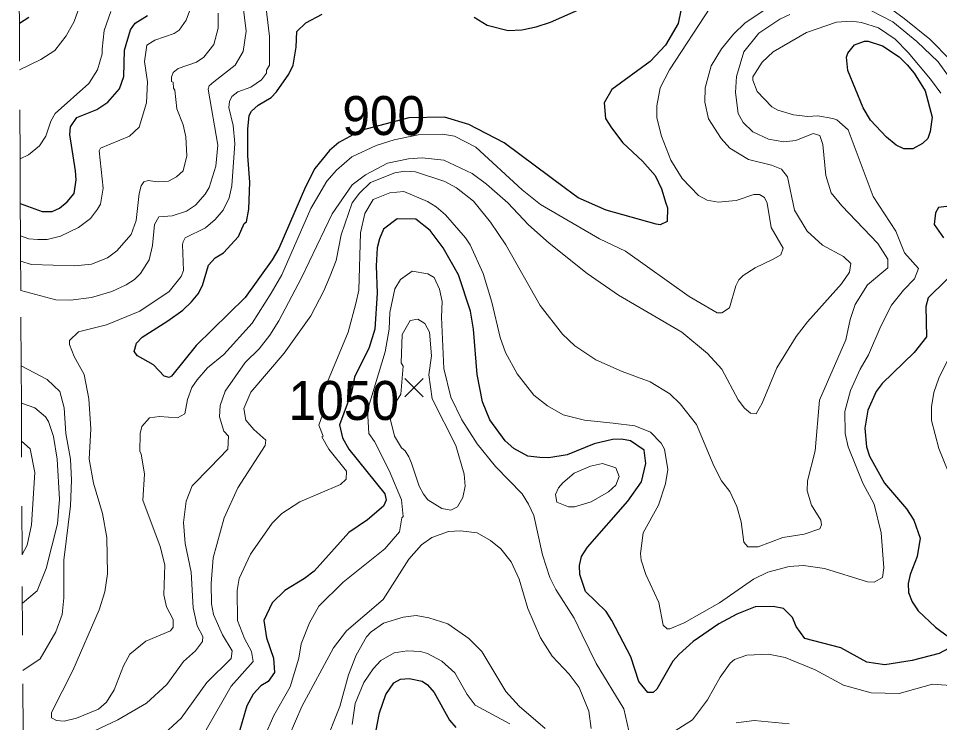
# Model space of a CAD drawing. Extents: x 423 to 448.8, y 7456.3 to 7484.
# Drawn here: x 423.014 to 424.902, y 7477.935 to 7479.378 of the extents above; entities that cross this region are included whole.
import ezdxf
from ezdxf.enums import TextEntityAlignment as Align

# ---------------------------------------------------------------- set-up
doc = ezdxf.new("R2010")
doc.units = 0
doc.header["$LTSCALE"] = 0.032
doc.linetypes.add('SHORT_DASHED', pattern=[2.7, 1.5, -1.2])
for name, color, linetype, lineweight in [('1', 7, 'Continuous', 25), ('2', 7, 'Continuous', 13), ('21', 7, 'Continuous', 25), ('22', 7, 'SHORT_DASHED', 13)]:
    doc.layers.add(name, color=color, linetype=linetype, lineweight=lineweight)
doc.layers.add('61', color=7, linetype='Continuous')

msp = doc.modelspace()

# ---------------------------------------------------------------- linework, layer by layer
at = {"layer": '1'}
for points in [[(423.9483, 7479.3807), (423.9746, 7479.3645), (424.0179, 7479.3536), (424.0458, 7479.3551), (424.0752, 7479.3614), (424.1046, 7479.3706), (424.1974, 7479.4116)], [(423.0356, 7479.3799), (423.0163, 7479.3681)], [(423.0182, 7478.9991), (423.0627, 7478.9824), (423.0697, 7478.9824), (423.0835, 7478.9827), (423.0983, 7478.9893), (423.1141, 7479.0025), (423.1284, 7479.0195), (423.1323, 7479.0473), (423.1315, 7479.0659), (423.1199, 7479.1402), (423.1207, 7479.1564), (423.1338, 7479.1749), (423.1749, 7479.1919), (423.1973, 7479.2067), (423.2213, 7479.2337), (423.2305, 7479.2593), (423.232, 7479.3134), (423.2437, 7479.3552), (423.2537, 7479.3683), (423.2785, 7479.3845)], [(424.3714, 7479.3946), (424.366, 7479.3676), (424.3404, 7479.3234), (424.3087, 7479.2902), (424.2306, 7479.2329), (424.2144, 7479.2051), (424.2175, 7479.1734), (424.2298, 7479.1541), (424.253, 7479.1231), (424.2932, 7479.086), (424.3188, 7479.0566), (424.3319, 7479.0288), (424.3413, 7478.9997), (424.3443, 7478.9901), (424.3435, 7478.9622), (424.3296, 7478.9553), (424.3211, 7478.9568), (424.219, 7478.9855), (424.161, 7479.0102), (424.1354, 7479.0295), (424.0094, 7479.1231), (423.9375, 7479.161), (423.8875, 7479.176), (423.8143, 7479.1747), (423.7163, 7479.1485), (423.6706, 7479.1239), (423.652, 7479.1076), (423.6219, 7479.0706), (423.6025, 7479.0334), (423.5476, 7478.9066), (423.5345, 7478.8833), (423.4788, 7478.806), (423.3783, 7478.7078), (423.328, 7478.6451), (423.3233, 7478.642), (423.3133, 7478.6451), (423.2908, 7478.6683), (423.2584, 7478.6869), (423.2514, 7478.6954), (423.2561, 7478.7124), (423.2676, 7478.7248), (423.3202, 7478.7581), (423.3512, 7478.7805), (423.369, 7478.7975), (423.3829, 7478.8138), (423.3914, 7478.8308), (423.4038, 7478.8725), (423.4177, 7478.8872), (423.4347, 7478.898), (423.4656, 7478.9313), (423.4772, 7478.9576), (423.4819, 7478.9615), (423.4865, 7478.987), (423.4888, 7479.0427), (423.4842, 7479.0968), (423.4842, 7479.151), (423.4873, 7479.1796), (423.492, 7479.1881), (423.5059, 7479.2005), (423.5322, 7479.2159), (423.543, 7479.2275), (423.5685, 7479.2639), (423.577, 7479.2825), (423.5832, 7479.3196), (423.5847, 7479.3513), (423.6034, 7479.3691), (423.6366, 7479.3869)], [(424.9275, 7478.994), (424.8997, 7478.9909), (424.8935, 7478.98), (424.8911, 7478.9561), (424.9097, 7478.9282)], [(424.0295, 7478.4966), (424.0117, 7478.5121), (423.98, 7478.5554), (423.9653, 7478.5926), (423.9545, 7478.6482), (423.9468, 7478.7411), (423.9406, 7478.7782), (423.9158, 7478.8524), (423.8849, 7478.9081), (423.8578, 7478.9437), (423.8284, 7478.9669), (423.7905, 7478.9677), (423.7627, 7478.946), (423.7542, 7478.9267), (423.7495, 7478.9081), (423.7472, 7478.871), (423.7495, 7478.8153), (423.7449, 7478.7411), (423.7333, 7478.7039), (423.7031, 7478.6428), (423.6969, 7478.6115), (423.6721, 7478.5453), (423.6782, 7478.5184), (423.6915, 7478.4951), (423.765, 7478.4038), (423.7678, 7478.3907), (423.7627, 7478.3783), (423.7294, 7478.3504), (423.6915, 7478.3241), (423.6203, 7478.2453), (423.6003, 7478.2298), (423.56, 7478.2058), (423.5345, 7478.1803), (423.5175, 7478.1439), (423.5229, 7478.1084), (423.5368, 7478.0666), (423.5391, 7478.0372), (423.526, 7478.0186), (423.5113, 7478.0101), (423.4951, 7477.9931), (423.4827, 7477.9691), (423.4587, 7477.8872)], [(424.9523, 7478.8779), (424.8788, 7478.8052), (424.8741, 7478.7875), (424.8749, 7478.7256), (424.8501, 7478.6931), (424.7844, 7478.6297), (424.772, 7478.6134), (424.755, 7478.5755), (424.7488, 7478.5384), (424.7519, 7478.4997), (424.7581, 7478.4812), (424.789, 7478.4255), (424.8339, 7478.3729), (424.8494, 7478.3497), (424.8625, 7478.3126), (424.8563, 7478.2754), (424.8416, 7478.2383), (424.8378, 7478.2197), (424.8386, 7478.2012), (424.8455, 7478.1826), (424.8579, 7478.1641), (424.8934, 7478.13), (424.9205, 7478.1107)], [(424.9205, 7478.0867), (424.9012, 7478.0766), (424.8455, 7478.0619), (424.7898, 7478.0534), (424.7527, 7478.0589), (424.6993, 7478.0882), (424.6259, 7478.1068), (424.608, 7478.1316), (424.6003, 7478.1501), (424.5818, 7478.1687), (424.5609, 7478.1725), (424.5238, 7478.1718), (424.4866, 7478.1571), (424.4495, 7478.1369), (424.3969, 7478.1006), (424.3683, 7478.0751), (424.3551, 7478.0604), (424.3226, 7478.0032), (424.3149, 7477.9962), (424.3041, 7477.9962), (424.2855, 7478.0186), (424.2693, 7478.0697), (424.2306, 7478.1439), (424.219, 7478.1625), (424.1765, 7478.2035), (424.1649, 7478.2383), (424.1641, 7478.2569), (424.168, 7478.2754), (424.1803, 7478.294), (424.2631, 7478.3884), (424.2909, 7478.4286), (424.3002, 7478.4657), (424.2964, 7478.4935), (424.2685, 7478.5121), (424.25, 7478.5159), (424.2314, 7478.5152), (424.1943, 7478.5059), (424.1386, 7478.4835), (424.1015, 7478.4773), (424.0829, 7478.4781), (424.0581, 7478.4811), (424.0295, 7478.4966)], [(423.7433, 7477.898), (423.7545, 7477.9544), (423.7673, 7477.9923), (423.7835, 7478.0163), (423.7975, 7478.024), (423.8153, 7478.0248), (423.8416, 7478.0194), (423.8524, 7478.0124), (423.8663, 7477.9962), (423.898, 7477.9398), (423.9104, 7477.9243)]]:
    msp.add_lwpolyline(points, dxfattribs=at)
msp.add_lwpolyline([(424.7453, 7479.195), (424.714, 7479.2717), (424.7109, 7479.2987), (424.714, 7479.3072), (424.7279, 7479.3242), (424.7481, 7479.332), (424.7558, 7479.332), (424.7852, 7479.3219), (424.8192, 7479.2995), (424.8354, 7479.2832), (424.8502, 7479.2662), (424.8726, 7479.2299), (424.8865, 7479.1757), (424.8826, 7479.1463), (424.878, 7479.1324), (424.8671, 7479.1216), (424.8471, 7479.1107), (424.8285, 7479.1107), (424.813, 7479.1185), (424.7929, 7479.1347), (424.7604, 7479.1695)], close=True, dxfattribs=at)
at = {"layer": '2'}
for points in [[(423.0168, 7479.2731), (423.0604, 7479.294), (423.089, 7479.3126), (423.1122, 7479.3428), (423.1284, 7479.3722), (423.147, 7479.4248)], [(423.4719, 7479.4248), (423.4811, 7479.3521), (423.4749, 7479.3103), (423.4587, 7479.2825), (423.4146, 7479.2484), (423.4053, 7479.2399), (423.403, 7479.233), (423.4231, 7479.1185), (423.4185, 7479.0752), (423.4053, 7479.0319), (423.3968, 7479.018), (423.3775, 7478.9955), (423.3589, 7478.9831), (423.3295, 7478.9739), (423.3017, 7478.9715), (423.2932, 7478.9561), (423.2893, 7478.9128), (423.2823, 7478.8834), (423.2645, 7478.8555), (423.2522, 7478.8431), (423.2352, 7478.8323), (423.2058, 7478.8184), (423.164, 7478.806), (423.1207, 7478.8006), (423.0913, 7478.8014), (423.0191, 7478.8202)], [(423.3667, 7479.3985), (423.3581, 7479.3745), (423.3435, 7479.3544), (423.3334, 7479.3474), (423.294, 7479.3335), (423.2777, 7479.3235), (423.273, 7479.2902), (423.2785, 7479.2484), (423.2769, 7479.2051), (423.2615, 7479.1556), (423.2421, 7479.137), (423.1826, 7479.1123), (423.1795, 7479.1069), (423.188, 7479.0303), (423.1826, 7478.9978), (423.1764, 7478.987), (423.1617, 7478.9684), (423.1377, 7478.9499), (423.1006, 7478.9321), (423.0735, 7478.9251), (423.0542, 7478.9251), (423.0356, 7478.9267), (423.0185, 7478.9325)], [(423.2669, 7478.5415), (423.2638, 7478.5276), (423.263, 7478.4905), (423.2661, 7478.4858), (423.273, 7478.444), (423.2692, 7478.3907), (423.3048, 7478.2955), (423.3141, 7478.2584), (423.3125, 7478.1965), (423.3179, 7478.1718), (423.3311, 7478.1462), (423.3311, 7478.13), (423.3257, 7478.123), (423.2754, 7478.1014), (423.2429, 7478.0751), (423.2297, 7478.0511), (423.2104, 7478.0016), (423.1949, 7477.9769), (423.1787, 7477.9621), (423.1331, 7477.9436), (423.1083, 7477.9374), (423.0921, 7477.9389), (423.082, 7477.9443), (423.082, 7477.9552), (423.1261, 7478.0418), (423.1795, 7478.1656), (423.1911, 7478.2027), (423.1965, 7478.2399), (423.1957, 7478.3141), (423.1864, 7478.3636), (423.1679, 7478.4255), (423.1594, 7478.475), (423.1625, 7478.5369), (423.1586, 7478.5987), (423.1493, 7478.6482), (423.1284, 7478.6854), (423.1192, 7478.7101), (423.1192, 7478.7178), (423.1377, 7478.7356), (423.195, 7478.7503), (423.263, 7478.7781), (423.3234, 7478.8184), (423.3481, 7478.8493), (423.3527, 7478.8617), (423.3504, 7478.9151), (423.352, 7478.92), (423.3558, 7478.9282), (423.3976, 7478.9491), (423.4177, 7478.9661), (423.4339, 7478.9854), (423.4463, 7479.0102), (423.4517, 7479.035), (423.4579, 7479.1216), (423.4541, 7479.1587), (423.4456, 7479.1959), (423.4471, 7479.2082), (423.4517, 7479.2183), (423.4641, 7479.2275), (423.4904, 7479.2376), (423.5121, 7479.2523), (423.5229, 7479.2662), (423.5229, 7479.2724), (423.5291, 7479.2824), (423.5291, 7479.3413), (423.5198, 7479.4155)], [(423.1455, 7477.9065), (423.2182, 7477.9405), (423.2769, 7477.9745), (423.3187, 7478.0125), (423.3527, 7478.0596), (423.3775, 7478.0821), (423.3914, 7478.1006), (423.3922, 7478.1115), (423.3806, 7478.1331), (423.3721, 7478.1702), (423.3682, 7478.2429), (423.3558, 7478.3017), (423.3527, 7478.345), (423.3581, 7478.3884), (423.3705, 7478.4201), (423.4069, 7478.458), (423.4432, 7478.495), (423.4448, 7478.5221), (423.4355, 7478.5322), (423.4262, 7478.5616), (423.4277, 7478.5848), (423.4378, 7478.6142), (423.4788, 7478.673), (423.5074, 7478.7008), (423.5298, 7478.7287), (423.5476, 7478.7581), (423.5941, 7478.8462), (423.6575, 7478.9777), (423.6985, 7479.0373), (423.7256, 7479.0574), (423.7704, 7479.0814), (423.8137, 7479.0907), (423.8416, 7479.0922), (423.8864, 7479.0876), (423.9444, 7479.0605), (423.9738, 7479.0388), (424.0171, 7479.0001), (424.0597, 7478.9553), (424.1022, 7478.9174), (424.1796, 7478.8555), (424.2437, 7478.8107), (424.3737, 7478.7349), (424.4263, 7478.6915), (424.4557, 7478.6591), (424.4889, 7478.5964), (424.5021, 7478.5794), (424.5145, 7478.5693), (424.5261, 7478.5678), (424.5384, 7478.5895), (424.5686, 7478.6622), (424.608, 7478.7263), (424.6312, 7478.7565), (424.7009, 7478.8339), (424.7171, 7478.8578), (424.7202, 7478.8756), (424.7048, 7478.8903), (424.6622, 7478.9135), (424.6305, 7478.9422), (424.6049, 7478.9855), (424.5903, 7479.0535), (424.5779, 7479.069), (424.5578, 7479.0775), (424.5106, 7479.0891), (424.4719, 7479.1123), (424.4541, 7479.1324), (424.4286, 7479.1726), (424.4209, 7479.2067), (424.4217, 7479.2361), (424.434, 7479.2809), (424.4549, 7479.3157), (424.4797, 7479.3459), (424.5037, 7479.3691), (424.5624, 7479.4085)], [(424.4325, 7479.4015), (424.3482, 7479.2732), (424.3296, 7479.2361), (424.3227, 7479.1989), (424.3227, 7479.1742), (424.3319, 7479.1371), (424.3513, 7479.0876), (424.3745, 7479.0504), (424.4077, 7479.0156), (424.4255, 7479.0055), (424.448, 7479.0017), (424.4851, 7479.0048), (424.5214, 7479.0171), (424.533, 7479.0172), (424.5431, 7479.011), (424.5485, 7478.9994), (424.557, 7478.9499), (424.5817, 7478.9073), (424.5764, 7478.8934), (424.5609, 7478.8849), (424.5238, 7478.8671), (424.4998, 7478.8516), (424.4905, 7478.8423), (424.4843, 7478.83), (424.4712, 7478.7851), (424.4557, 7478.775), (424.4464, 7478.775), (424.3891, 7478.8083), (424.2584, 7478.9011), (424.2051, 7478.9266), (424.0844, 7478.997), (424.0465, 7479.0272), (423.9514, 7479.1146), (423.9081, 7479.137), (423.8833, 7479.1409), (423.8338, 7479.1394), (423.7843, 7479.1293), (423.7472, 7479.1177), (423.6977, 7479.0945), (423.666, 7479.0675), (423.6466, 7479.045), (423.6134, 7478.9886), (423.5538, 7478.8524), (423.5322, 7478.8153), (423.4935, 7478.7534), (423.4355, 7478.6892), (423.4015, 7478.6621), (423.3806, 7478.6374), (423.3697, 7478.6219), (423.3605, 7478.5972), (423.355, 7478.5678), (423.3404, 7478.5593), (423.3032, 7478.5624), (423.2831, 7478.5593), (423.2669, 7478.5415)], [(424.7836, 7479.4116), (424.8293, 7479.3783), (424.8818, 7479.3358), (424.9252, 7479.2918), (424.9731, 7479.2206), (424.9955, 7479.1757)], [(423.2034, 7479.3923), (423.1903, 7479.3536), (423.1857, 7479.315), (423.1857, 7479.3057), (423.1764, 7479.2732), (423.1586, 7479.2446), (423.0898, 7479.1834), (423.0805, 7479.168), (423.0704, 7479.1371), (423.0573, 7479.1169), (423.0348, 7479.0984), (423.0177, 7479.0907)], [(423.4239, 7479.3892), (423.4239, 7479.3583), (423.4146, 7479.325), (423.3945, 7479.2987), (423.379, 7479.2886), (423.3419, 7479.2755), (423.3311, 7479.2678), (423.328, 7479.2577), (423.328, 7479.2492), (423.3311, 7479.2476), (423.3318, 7479.2353), (423.3349, 7479.2314), (423.3388, 7479.1928), (423.3519, 7479.1603), (423.3574, 7479.1355), (423.3597, 7479.0968), (423.3519, 7479.0659), (423.338, 7479.0535), (423.3218, 7479.045), (423.3014, 7479.0436), (423.2943, 7479.0442), (423.28, 7479.0458), (423.2715, 7479.0435), (423.2661, 7479.035), (423.2615, 7479.0195), (423.2553, 7478.9638), (423.2452, 7478.9352), (423.2158, 7478.9019), (423.1965, 7478.8872), (423.164, 7478.8748), (423.13, 7478.871), (423.041, 7478.8737), (423.0188, 7478.8804)], [(424.6568, 7479.1386), (424.6429, 7479.1424), (424.6073, 7479.1278), (424.5826, 7479.1254), (424.5516, 7479.1308), (424.5191, 7479.1455), (424.4998, 7479.1649), (424.4889, 7479.1835), (424.4835, 7479.2268), (424.4858, 7479.2593), (424.5005, 7479.3095), (424.5315, 7479.3482), (424.5748, 7479.3768), (424.5949, 7479.3861)], [(424.7627, 7479.3939), (424.8061, 7479.3714), (424.8555, 7479.3312), (424.8989, 7479.2894), (424.9445, 7479.226)], [(424.8122, 7478.9422), (424.7658, 7479.0133), (424.7148, 7479.1502), (424.6916, 7479.1703), (424.6831, 7479.1734), (424.6522, 7479.1788), (424.6321, 7479.1772), (424.6027, 7479.1804), (424.5702, 7479.1904), (424.5585, 7479.1974), (424.5284, 7479.2283), (424.5191, 7479.2515), (424.5191, 7479.2585), (424.5384, 7479.2887), (424.5608, 7479.3095), (424.629, 7479.3497), (424.6908, 7479.3706), (424.7218, 7479.3729), (424.7419, 7479.3698), (424.7767, 7479.359), (424.8107, 7479.3358), (424.8378, 7479.3088), (424.8834, 7479.2538), (424.9043, 7479.2252)], [(423.3048, 7477.9041), (423.3481, 7477.9436), (423.4007, 7478.0171), (423.4502, 7478.0658), (423.4525, 7478.0821), (423.4324, 7478.1146), (423.4138, 7478.1563), (423.4099, 7478.178), (423.4092, 7478.2197), (423.4131, 7478.2723), (423.4362, 7478.3543), (423.4641, 7478.4162), (423.5198, 7478.5028), (423.5214, 7478.5137), (423.4966, 7478.5353), (423.4803, 7478.5546), (423.4765, 7478.5786), (423.4904, 7478.6119), (423.5592, 7478.6923), (423.6134, 7478.7689), (423.6404, 7478.8199), (423.6528, 7478.8509), (423.6652, 7478.8818), (423.676, 7478.9344), (423.6985, 7479.0001), (423.7131, 7479.0202), (423.7356, 7479.0419), (423.7859, 7479.062), (423.806, 7479.0651), (423.8277, 7479.0636), (423.888, 7479.0442), (423.9119, 7479.0311), (423.9468, 7479.004), (423.9816, 7478.9607), (424.0132, 7478.9143), (424.0836, 7478.7898), (424.1293, 7478.731), (424.1548, 7478.707), (424.1974, 7478.6784), (424.2515, 7478.6544), (424.3087, 7478.6335), (424.3489, 7478.6088), (424.3706, 7478.5879), (424.4038, 7478.5461), (424.4394, 7478.4611), (424.4549, 7478.4301), (424.4719, 7478.4085), (424.4866, 7478.3775), (424.4951, 7478.3466), (424.5006, 7478.3048), (424.509, 7478.2947), (424.53, 7478.2947), (424.581, 7478.3141), (424.6243, 7478.321), (424.6568, 7478.3319), (424.6599, 7478.3404), (424.6583, 7478.3497), (424.6398, 7478.3806), (424.6305, 7478.41), (424.6312, 7478.4301), (424.6467, 7478.492), (424.656, 7478.5956), (424.7101, 7478.7194), (424.7187, 7478.7612), (424.7287, 7478.7921), (424.7543, 7478.8323), (424.796, 7478.8671), (424.796, 7478.8849), (424.7751, 7478.9166), (424.7017, 7478.994), (424.68, 7479.021), (424.6692, 7479.0566), (424.663, 7479.1201), (424.6568, 7479.1386)], [(423.3992, 7477.9196), (423.4502, 7478.0093), (423.4951, 7478.0596), (423.492, 7478.0805), (423.4773, 7478.1068), (423.4633, 7478.1439), (423.4626, 7478.2058), (423.4664, 7478.2298), (423.4896, 7478.2801), (423.5345, 7478.3435), (423.5538, 7478.3636), (423.591, 7478.3876), (423.6745, 7478.4231), (423.6861, 7478.434), (423.6868, 7478.4502), (423.6505, 7478.4951), (423.6358, 7478.5206), (423.6385, 7478.5216), (423.6302, 7478.5442), (423.6377, 7478.5655), (423.6377, 7478.609), (423.69, 7478.7349), (423.7054, 7478.7937), (423.7116, 7478.8215), (423.7155, 7478.9391), (423.724, 7478.9785), (423.741, 7479.0071), (423.7751, 7479.021), (423.8044, 7479.0233), (423.8524, 7479.0032), (423.8702, 7478.9924), (423.8895, 7478.9754), (423.9305, 7478.9282), (423.9398, 7478.9143), (423.9669, 7478.8555), (423.9846, 7478.7967), (424.0016, 7478.724), (424.0125, 7478.6931), (424.0365, 7478.6498), (424.0705, 7478.6057), (424.0984, 7478.584), (424.1308, 7478.5654), (424.1742, 7478.5546), (424.2329, 7478.5484), (424.2778, 7478.543), (424.3095, 7478.5299), (424.3312, 7478.5074), (424.3381, 7478.4951), (424.3451, 7478.4533), (424.3404, 7478.4239), (424.3257, 7478.3806), (424.2948, 7478.3234), (424.2894, 7478.2816), (424.2901, 7478.2677), (424.3002, 7478.2383), (424.3265, 7478.1811), (424.3358, 7478.1346), (424.3435, 7478.1269), (424.349, 7478.1269), (424.3784, 7478.1393), (424.4511, 7478.1803), (424.5207, 7478.229), (424.5501, 7478.2429), (424.5934, 7478.2545), (424.6228, 7478.2568), (424.6661, 7478.2507), (424.7543, 7478.2236), (424.7682, 7478.2228), (424.7852, 7478.2321), (424.7875, 7478.2522), (424.7821, 7478.3234), (424.7682, 7478.3822), (424.7449, 7478.4255), (424.7148, 7478.4997), (424.7086, 7478.5276), (424.7078, 7478.5724), (424.7194, 7478.6158), (424.7395, 7478.6591), (424.7565, 7478.6885), (424.7813, 7478.7472), (424.8037, 7478.7906), (424.8277, 7478.8215), (424.8509, 7478.8447), (424.8587, 7478.8656), (424.83, 7478.898), (424.8122, 7478.9422)], [(424.2654, 7477.9181), (424.2546, 7477.963), (424.1981, 7478.0558), (424.1695, 7478.1146), (424.1532, 7478.1486), (424.1153, 7478.2074), (424.103, 7478.2321), (424.0883, 7478.2785), (424.0705, 7478.359), (424.0597, 7478.3822), (424.0465, 7478.4038), (423.9916, 7478.4595), (423.9545, 7478.5059), (423.9228, 7478.5554), (423.9003, 7478.6018), (423.8864, 7478.6606), (423.881, 7478.7658), (423.8825, 7478.7983), (423.8771, 7478.823), (423.8663, 7478.847), (423.8532, 7478.8547), (423.8214, 7478.8602), (423.7975, 7478.8431), (423.7859, 7478.8238), (423.7751, 7478.7751), (423.7743, 7478.7411), (423.7658, 7478.6946), (423.7293, 7478.5755), (423.7323, 7478.5275), (423.7443, 7478.511), (423.7743, 7478.4518), (423.799, 7478.3915), (423.8029, 7478.3574), (423.7998, 7478.3543), (423.7951, 7478.3257), (423.765, 7478.2909), (423.6799, 7478.2228), (423.6296, 7478.1733), (423.611, 7478.1393), (423.594, 7478.096), (423.5886, 7478.0666), (423.5709, 7478.0078), (423.5376, 7477.949), (423.5182, 7477.9042)], [(424.9283, 7478.6977), (424.9004, 7478.6405), (424.8903, 7478.6111), (424.8857, 7478.5817), (424.8857, 7478.5539), (424.9004, 7478.4966), (424.9298, 7478.4239)], [(423.0199, 7478.6662), (423.0735, 7478.6382), (423.099, 7478.6134), (423.1083, 7478.5802), (423.1114, 7478.5276), (423.1207, 7478.475), (423.123, 7478.4317), (423.1207, 7478.3791), (423.1075, 7478.2677), (423.1075, 7478.1904), (423.1037, 7478.1563), (423.0913, 7478.1207), (423.0588, 7478.0651), (423.0231, 7478.0412)], [(423.0203, 7478.5895), (423.048, 7478.5802), (423.0697, 7478.5616), (423.0758, 7478.5523), (423.0859, 7478.5214), (423.0936, 7478.475), (423.0982, 7478.393), (423.0944, 7478.342), (423.0712, 7478.2506), (423.0526, 7478.205), (423.0224, 7478.1796)], [(423.0207, 7478.5119), (423.0387, 7478.4958), (423.048, 7478.4471), (423.041, 7478.3404), (423.0325, 7478.2986), (423.0219, 7478.2791)], [(424.1881, 7477.9227), (424.1834, 7477.9583), (424.1633, 7478.0063), (424.1432, 7478.0341), (424.1084, 7478.0712), (424.0844, 7478.1084), (424.0581, 7478.1687), (424.0403, 7478.229), (424.0241, 7478.2646), (424.0032, 7478.2909), (423.9816, 7478.3079), (423.9545, 7478.3234), (423.9205, 7478.328), (423.8957, 7478.3265), (423.8617, 7478.3141), (423.84, 7478.2994), (423.8145, 7478.27), (423.7619, 7478.1873), (423.6869, 7478.123), (423.6598, 7478.0882), (423.5948, 7477.9676), (423.5693, 7477.9073)], [(424.0937, 7477.9227), (424.0403, 7477.9683), (424.0133, 7477.9985), (423.9637, 7478.0805), (423.9375, 7478.1068), (423.8942, 7478.137), (423.8555, 7478.1493), (423.8292, 7478.154), (423.8029, 7478.1509), (423.7627, 7478.1385), (423.7371, 7478.1207), (423.7279, 7478.1107), (423.7062, 7478.0728), (423.6907, 7478.0326), (423.673, 7477.9676), (423.6405, 7477.8872)], [(423.6985, 7477.9305), (423.7046, 7477.9738), (423.7224, 7478.0171), (423.741, 7478.0449), (423.7573, 7478.062), (423.7843, 7478.0774), (423.8106, 7478.0821), (423.8385, 7478.0805), (423.8524, 7478.0766), (423.8818, 7478.0604), (423.9088, 7478.0364), (423.9336, 7477.9923), (423.9506, 7477.9707), (424.021, 7477.932)], [(424.9337, 7478.0101), (424.8873, 7478.0132), (424.8192, 7477.9946), (424.762, 7477.9954), (424.7048, 7478.0117), (424.6467, 7478.0426), (424.5856, 7478.0681), (424.5516, 7478.0751), (424.5068, 7478.0728), (424.482, 7478.0642), (424.4727, 7478.0565), (424.4526, 7478.0279), (424.4263, 7477.9815), (424.3954, 7477.9405), (424.3474, 7477.9096)], [(424.5934, 7477.932), (424.5222, 7477.939), (424.4851, 7477.9343)]]:
    msp.add_lwpolyline(points, dxfattribs=at)
for points in [[(423.8195, 7478.4664), (423.8145, 7478.4796), (423.8068, 7478.492), (423.799, 7478.4981), (423.7851, 7478.5222), (423.7768, 7478.5553), (423.7836, 7478.5846), (423.7979, 7478.6079), (423.8024, 7478.6654), (423.7983, 7478.6722), (423.8005, 7478.7302), (423.8168, 7478.7588), (423.833, 7478.7619), (423.847, 7478.7526), (423.857, 7478.7349), (423.8609, 7478.6869), (423.8556, 7478.6473), (423.8624, 7478.5985), (423.9104, 7478.5028), (423.9274, 7478.444), (423.9297, 7478.4193), (423.9251, 7478.3961), (423.9143, 7478.3767), (423.9003, 7478.3705), (423.8817, 7478.3736), (423.8532, 7478.3914), (423.8446, 7478.403), (423.8354, 7478.4193)], [(424.13, 7478.4262), (424.1533, 7478.4463), (424.1865, 7478.4603), (424.2113, 7478.4657), (424.2383, 7478.4572), (424.2453, 7478.4394), (424.2383, 7478.4216), (424.2237, 7478.4077), (424.1881, 7478.3876), (424.1541, 7478.3767), (424.1417, 7478.3767), (424.1177, 7478.3868), (424.1146, 7478.4023), (424.1208, 7478.4162)]]:
    msp.add_lwpolyline(points, close=True, dxfattribs=at)
at = {"layer": '21'}
for p, q in [((423.8059, 7478.64), (423.8434, 7478.6025)), ((423.8434, 7478.64), (423.8059, 7478.6025))]:
    msp.add_line(p, q, dxfattribs=at)
at = {"layer": '22'}
for points in [[(423.0163, 7479.3681), (423.0161, 7479.4084), (423.0159, 7479.4473), (423.0143, 7479.7688)], [(423.0191, 7478.8202), (423.019, 7478.8436), (423.0188, 7478.8804), (423.0185, 7478.9325), (423.0182, 7478.9991), (423.0177, 7479.0907), (423.0163, 7479.3681)], [(423.0275, 7477.1635), (423.0247, 7477.7139), (423.0219, 7478.2787), (423.0207, 7478.5119), (423.0203, 7478.5895), (423.0199, 7478.6662), (423.0191, 7478.8202)]]:
    msp.add_lwpolyline(points, dxfattribs=at)

# ---------------------------------------------------------------- texts
at = {"layer": '61', "width": 0.95}
for s, p in [('900', (423.7629, 7479.1392)), ('1050', (423.6811, 7478.5551))]:
    msp.add_text(s, height=0.08, dxfattribs=at).set_placement(p, align=Align.CENTER)

doc.saveas('drawing.dxf')
